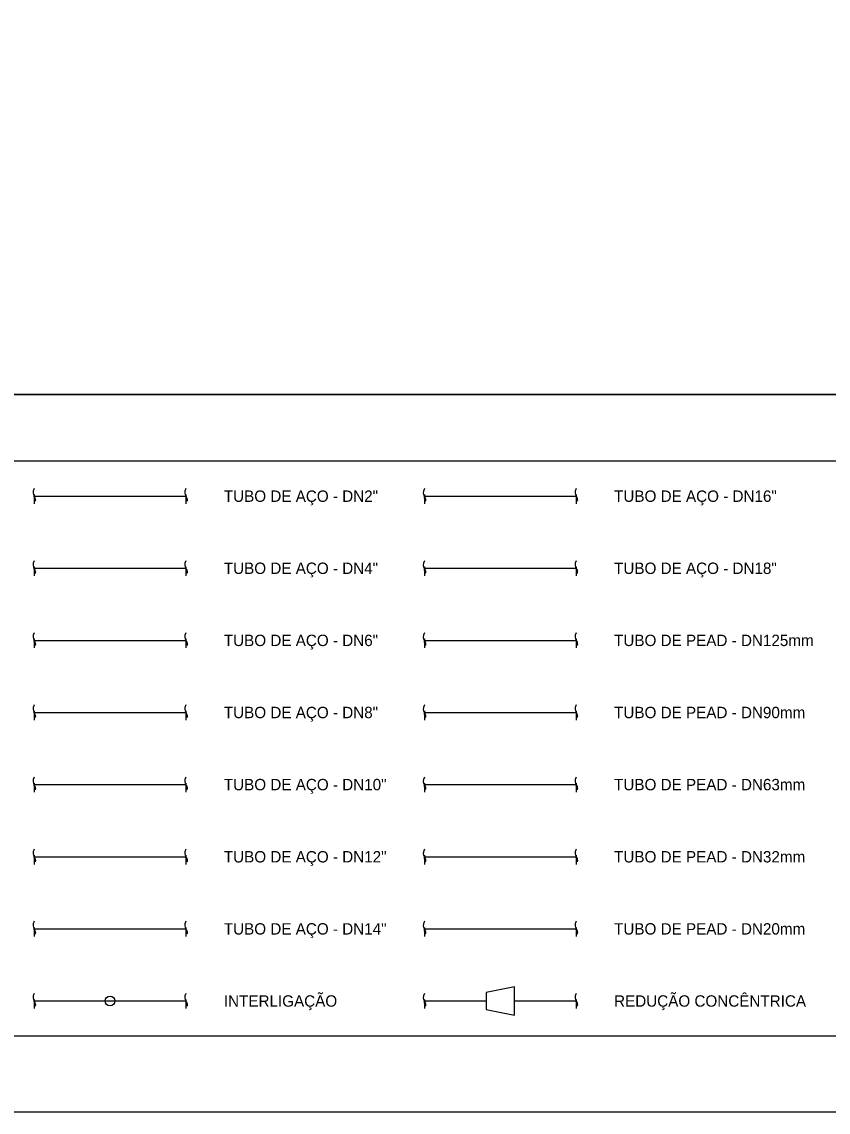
# Model space of a CAD drawing. Extents: x 0 to 841, y 0 to 594.
# Drawn here: x 211.4 to 317.6, y 0 to 143.7 of the extents above; entities that cross this region are included whole.
import ezdxf

# ---------------------------------------------------------------- set-up
doc = ezdxf.new("R2010")
doc.units = 0
for name, color, linetype in [('FORMATO', 7, 'Continuous'), ('LEGENDA', 7, 'Continuous'), ('MEIO_FIO_GUIA', 7, 'Continuous'), ('TUBO_ACO_GN_10', 7, 'Continuous'), ('TUBO_ACO_GN_12', 7, 'Continuous'), ('TUBO_ACO_GN_14', 7, 'Continuous'), ('TUBO_ACO_GN_16', 7, 'Continuous'), ('TUBO_ACO_GN_18', 7, 'Continuous'), ('TUBO_ACO_GN_2', 7, 'Continuous'), ('TUBO_ACO_GN_4', 7, 'Continuous'), ('TUBO_ACO_GN_6', 7, 'Continuous'), ('TUBO_ACO_GN_8', 7, 'Continuous'), ('TUBO_PEAD_GN_125', 7, 'Continuous'), ('TUBO_PEAD_GN_20', 7, 'Continuous'), ('TUBO_PEAD_GN_32', 7, 'Continuous'), ('TUBO_PEAD_GN_63', 7, 'Continuous'), ('TUBO_PEAD_GN_90', 7, 'Continuous')]:
    doc.layers.add(name, color=color, linetype=linetype)

msp = doc.modelspace()

# ---------------------------------------------------------------- linework, layer by layer
at = {"layer": 'FORMATO'}
for p, q in [((831.01, 94.54), (25, 94.54)), ((25, 85.81), (656, 85.81)), ((831.01, 10), (5, 10))]:
    msp.add_line(p, q, dxfattribs=at)
msp.add_lwpolyline([(0, 594), (841, 594), (841, 0), (0, 0)], close=True, dxfattribs=at)
at = {"layer": 'LEGENDA'}
for p, q in [((213, 14.65), (233, 14.65)), ((264.43, 14.65), (272.55, 14.65)), ((276.3, 14.65), (284.43, 14.65))]:
    msp.add_line(p, q, dxfattribs=at)
msp.add_lwpolyline([(276.3, 16.53), (272.55, 15.78), (272.55, 13.53), (276.3, 12.78)], close=True, dxfattribs=at)
msp.add_circle((223, 14.65), 0.633, dxfattribs=at)
for points in [[(213, 15.65), (212.75, 15.15), (213, 14.65), (213.25, 14.15), (213, 13.65), (213, 15.65), (213, 13.65)], [(233, 15.65), (232.75, 15.15), (233, 14.65), (233.25, 14.15), (233, 13.65), (233, 15.65), (233, 13.65)], [(264.43, 15.65), (264.18, 15.15), (264.43, 14.65), (264.68, 14.15), (264.43, 13.65), (264.43, 15.65), (264.43, 13.65)], [(284.43, 15.65), (284.18, 15.15), (284.43, 14.65), (284.68, 14.15), (284.43, 13.65), (284.43, 15.65), (284.43, 13.65)]]:
    msp.add_open_spline(points, degree=3, dxfattribs=at)
at = {"layer": 'MEIO_FIO_GUIA'}
msp.add_lwpolyline([(25, 584), (25, 94.54), (572.92, 94.54), (831.01, 94.54), (831.01, 251.27), (831.01, 584)], close=True, dxfattribs=at)
at = {"layer": 'TUBO_ACO_GN_10'}
msp.add_line((213, 43.16), (233, 43.16), dxfattribs=at)
for points in [[(213, 44.16), (212.75, 43.66), (213, 43.16), (213.25, 42.66), (213, 42.16), (213, 44.16), (213, 42.16)], [(233, 44.16), (232.75, 43.66), (233, 43.16), (233.25, 42.66), (233, 42.16), (233, 44.16), (233, 42.16)]]:
    msp.add_open_spline(points, degree=3, dxfattribs=at)
at = {"layer": 'TUBO_ACO_GN_12'}
msp.add_line((213, 33.65), (233, 33.65), dxfattribs=at)
for points in [[(213, 34.65), (212.75, 34.15), (213, 33.65), (213.25, 33.15), (213, 32.65), (213, 34.65), (213, 32.65)], [(233, 34.65), (232.75, 34.15), (233, 33.65), (233.25, 33.15), (233, 32.65), (233, 34.65), (233, 32.65)]]:
    msp.add_open_spline(points, degree=3, dxfattribs=at)
at = {"layer": 'TUBO_ACO_GN_14'}
msp.add_line((213, 24.15), (233, 24.15), dxfattribs=at)
for points in [[(213, 25.15), (212.75, 24.65), (213, 24.15), (213.25, 23.65), (213, 23.15), (213, 25.15), (213, 23.15)], [(233, 25.15), (232.75, 24.65), (233, 24.15), (233.25, 23.65), (233, 23.15), (233, 25.15), (233, 23.15)]]:
    msp.add_open_spline(points, degree=3, dxfattribs=at)
at = {"layer": 'TUBO_ACO_GN_16'}
msp.add_line((264.43, 81.16), (284.43, 81.16), dxfattribs=at)
for points in [[(264.43, 82.16), (264.18, 81.66), (264.43, 81.16), (264.68, 80.66), (264.43, 80.16), (264.43, 82.16), (264.43, 80.16)], [(284.43, 82.16), (284.18, 81.66), (284.43, 81.16), (284.68, 80.66), (284.43, 80.16), (284.43, 82.16), (284.43, 80.16)]]:
    msp.add_open_spline(points, degree=3, dxfattribs=at)
at = {"layer": 'TUBO_ACO_GN_18'}
msp.add_line((264.43, 71.66), (284.43, 71.66), dxfattribs=at)
for points in [[(264.43, 72.66), (264.18, 72.16), (264.43, 71.66), (264.68, 71.16), (264.43, 70.66), (264.43, 72.66), (264.43, 70.66)], [(284.43, 72.66), (284.18, 72.16), (284.43, 71.66), (284.68, 71.16), (284.43, 70.66), (284.43, 72.66), (284.43, 70.66)]]:
    msp.add_open_spline(points, degree=3, dxfattribs=at)
at = {"layer": 'TUBO_ACO_GN_2'}
msp.add_line((213, 81.16), (233, 81.16), dxfattribs=at)
for points in [[(213, 82.16), (212.75, 81.66), (213, 81.16), (213.25, 80.66), (213, 80.16), (213, 82.16), (213, 80.16)], [(233, 82.16), (232.75, 81.66), (233, 81.16), (233.25, 80.66), (233, 80.16), (233, 82.16), (233, 80.16)]]:
    msp.add_open_spline(points, degree=3, dxfattribs=at)
at = {"layer": 'TUBO_ACO_GN_4'}
msp.add_line((213, 71.66), (233, 71.66), dxfattribs=at)
for points in [[(213, 72.66), (212.75, 72.16), (213, 71.66), (213.25, 71.16), (213, 70.66), (213, 72.66), (213, 70.66)], [(233, 72.66), (232.75, 72.16), (233, 71.66), (233.25, 71.16), (233, 70.66), (233, 72.66), (233, 70.66)]]:
    msp.add_open_spline(points, degree=3, dxfattribs=at)
at = {"layer": 'TUBO_ACO_GN_6'}
msp.add_line((213, 62.16), (233, 62.16), dxfattribs=at)
for points in [[(213, 63.16), (212.75, 62.66), (213, 62.16), (213.25, 61.66), (213, 61.16), (213, 63.16), (213, 61.16)], [(233, 63.16), (232.75, 62.66), (233, 62.16), (233.25, 61.66), (233, 61.16), (233, 63.16), (233, 61.16)]]:
    msp.add_open_spline(points, degree=3, dxfattribs=at)
at = {"layer": 'TUBO_ACO_GN_8'}
msp.add_line((213, 52.66), (233, 52.66), dxfattribs=at)
for points in [[(213, 53.66), (212.75, 53.16), (213, 52.66), (213.25, 52.16), (213, 51.66), (213, 53.66), (213, 51.66)], [(233, 53.66), (232.75, 53.16), (233, 52.66), (233.25, 52.16), (233, 51.66), (233, 53.66), (233, 51.66)]]:
    msp.add_open_spline(points, degree=3, dxfattribs=at)
at = {"layer": 'TUBO_PEAD_GN_125'}
msp.add_line((264.43, 62.16), (284.43, 62.16), dxfattribs=at)
for points in [[(264.43, 63.16), (264.18, 62.66), (264.43, 62.16), (264.68, 61.66), (264.43, 61.16), (264.43, 63.16), (264.43, 61.16)], [(284.43, 63.16), (284.18, 62.66), (284.43, 62.16), (284.68, 61.66), (284.43, 61.16), (284.43, 63.16), (284.43, 61.16)]]:
    msp.add_open_spline(points, degree=3, dxfattribs=at)
at = {"layer": 'TUBO_PEAD_GN_20'}
msp.add_line((264.43, 24.15), (284.43, 24.15), dxfattribs=at)
for points in [[(264.43, 25.15), (264.18, 24.65), (264.43, 24.15), (264.68, 23.65), (264.43, 23.15), (264.43, 25.15), (264.43, 23.15)], [(284.43, 25.15), (284.18, 24.65), (284.43, 24.15), (284.68, 23.65), (284.43, 23.15), (284.43, 25.15), (284.43, 23.15)]]:
    msp.add_open_spline(points, degree=3, dxfattribs=at)
at = {"layer": 'TUBO_PEAD_GN_32'}
msp.add_line((264.43, 33.65), (284.43, 33.65), dxfattribs=at)
for points in [[(264.43, 34.65), (264.18, 34.15), (264.43, 33.65), (264.68, 33.15), (264.43, 32.65), (264.43, 34.65), (264.43, 32.65)], [(284.43, 34.65), (284.18, 34.15), (284.43, 33.65), (284.68, 33.15), (284.43, 32.65), (284.43, 34.65), (284.43, 32.65)]]:
    msp.add_open_spline(points, degree=3, dxfattribs=at)
at = {"layer": 'TUBO_PEAD_GN_63'}
msp.add_line((264.43, 43.16), (284.43, 43.16), dxfattribs=at)
for points in [[(264.43, 44.16), (264.18, 43.66), (264.43, 43.16), (264.68, 42.66), (264.43, 42.16), (264.43, 44.16), (264.43, 42.16)], [(284.43, 44.16), (284.18, 43.66), (284.43, 43.16), (284.68, 42.66), (284.43, 42.16), (284.43, 44.16), (284.43, 42.16)]]:
    msp.add_open_spline(points, degree=3, dxfattribs=at)
at = {"layer": 'TUBO_PEAD_GN_90'}
msp.add_line((264.43, 52.66), (284.43, 52.66), dxfattribs=at)
for points in [[(264.43, 53.66), (264.18, 53.16), (264.43, 52.66), (264.68, 52.16), (264.43, 51.66), (264.43, 53.66), (264.43, 51.66)], [(284.43, 53.66), (284.18, 53.16), (284.43, 52.66), (284.68, 52.16), (284.43, 51.66), (284.43, 53.66), (284.43, 51.66)]]:
    msp.add_open_spline(points, degree=3, dxfattribs=at)

# ---------------------------------------------------------------- texts
at = {"layer": 'LEGENDA'}
for s, p in [('TUBO DE AÇO - DN2"', (238, 80.41)), ('TUBO DE AÇO - DN16"', (289.43, 80.41)), ('TUBO DE AÇO - DN4"', (238, 70.91)), ('TUBO DE AÇO - DN18"', (289.43, 70.91)), ('TUBO DE AÇO - DN6"', (238, 61.41)), ('TUBO DE PEAD - DN125mm', (289.43, 61.41)), ('TUBO DE AÇO - DN8"', (238, 51.91)), ('TUBO DE PEAD - DN90mm', (289.43, 51.91)), ('TUBO DE AÇO - DN10"', (238, 42.41)), ('TUBO DE PEAD - DN63mm', (289.43, 42.41)), ('TUBO DE AÇO - DN12"', (238, 32.9)), ('TUBO DE PEAD - DN32mm', (289.43, 32.9)), ('TUBO DE AÇO - DN14"', (238, 23.4)), ('TUBO DE PEAD - DN20mm', (289.43, 23.4)), ('INTERLIGAÇÃO', (238, 13.9)), ('REDUÇÃO CONCÊNTRICA', (289.43, 13.9))]:
    msp.add_text(s, height=1.5, dxfattribs=at).set_placement(p)

doc.saveas('drawing.dxf')
